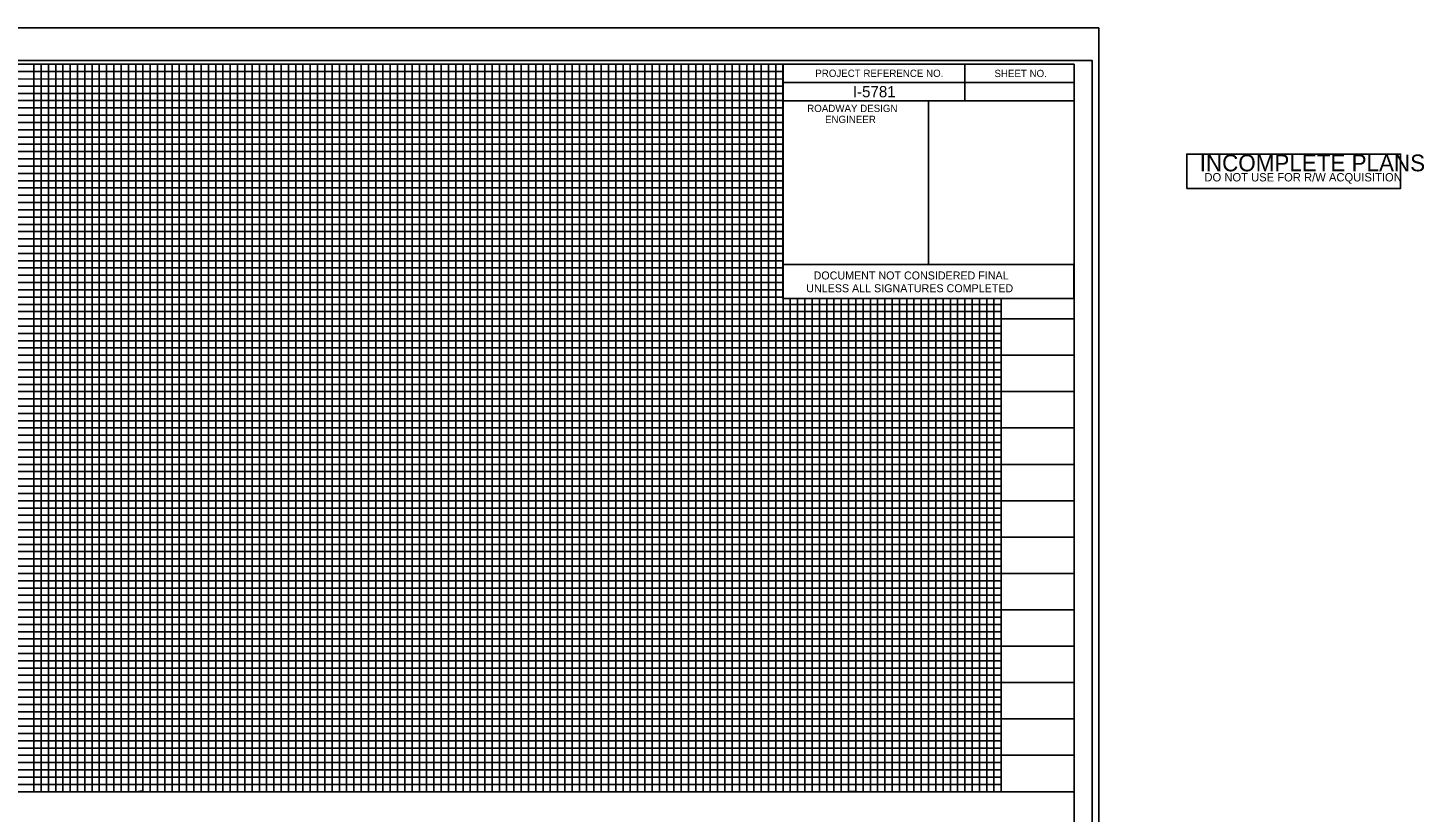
# Model space of a CAD drawing. Extents: x 2327371 to 2329279, y 159556 to 160656.
# Drawn here: x 2328319 to 2329279, y 160117 to 160656 of the extents above; entities that cross this region are included whole.
import ezdxf

# ---------------------------------------------------------------- set-up
doc = ezdxf.new("R2010")
doc.units = 0
for name, color, linetype in [('Scratch_Level_0', 7, 'Continuous'), ('Sheet Cutting Line CELL', 7, 'Continuous'), ('Sheet Data Field CELL', 7, 'Continuous'), ('Sheet DOT Grid CELL', 7, 'Continuous'), ('Sheet Layout Profile Border Port 1', 7, 'Continuous'), ('Sheet Plot Border Inside CELL', 7, 'Continuous'), ('Sheet Plot Border Outside CELL', 7, 'Continuous'), ('Sheet Profile CELL', 7, 'Continuous'), ('Sheet Profile Grid Major CELL', 7, 'Continuous'), ('Sheet Profile Grid Middle CELL', 7, 'Continuous'), ('Sheet Profile Grid Minor CELL', 7, 'Continuous'), ('Sheet Sticker Exception Certification CELL', 7, 'Continuous'), ('Sheet Sticker Incomplete CELL', 7, 'Continuous')]:
    doc.layers.add(name, color=color, linetype=linetype)

msp = doc.modelspace()

# ---------------------------------------------------------------- linework, layer by layer
at = {"layer": 'Scratch_Level_0'}
msp.add_lwpolyline([(2327587.98, 160131.31), (2327587.98, 160631.31), (2328837.98, 160631.31), (2328837.98, 160470.26), (2328987.98, 160470.26), (2328987.98, 160131.31)], close=True, dxfattribs=at)
at = {"layer": 'Sheet Cutting Line CELL'}
msp.add_line((2329054.98, 160656.31), (2327370.98, 160656.31), dxfattribs=at)
at = {"layer": 'Sheet DOT Grid CELL'}
for p, q in [((2328337.98, 160131.31), (2328337.98, 160631.31)), ((2328387.98, 160131.31), (2328387.98, 160631.31)), ((2328437.98, 160131.31), (2328437.98, 160631.31)), ((2328487.98, 160131.31), (2328487.98, 160631.31)), ((2328537.98, 160131.31), (2328537.98, 160631.31)), ((2328587.98, 160131.31), (2328587.98, 160631.31)), ((2328637.98, 160131.31), (2328637.98, 160631.31)), ((2328687.98, 160131.31), (2328687.98, 160631.31)), ((2328737.98, 160131.31), (2328737.98, 160631.31)), ((2328787.98, 160131.31), (2328787.98, 160631.31)), ((2328837.93, 160581.31), (2327537.98, 160581.31)), ((2328837.93, 160531.31), (2327537.98, 160531.31)), ((2328837.98, 160131.31), (2328837.98, 160493.76)), ((2328837.98, 160481.31), (2327537.98, 160481.31)), ((2328887.98, 160131.31), (2328887.98, 160470.26)), ((2328937.98, 160131.31), (2328937.98, 160470.26)), ((2328987.98, 160131.31), (2328987.98, 160470.26)), ((2329037.98, 160431.31), (2327537.98, 160431.31)), ((2329037.98, 160381.31), (2327537.98, 160381.31)), ((2329037.98, 160331.31), (2327537.98, 160331.31)), ((2329037.98, 160281.31), (2327537.98, 160281.31)), ((2329037.98, 160231.31), (2327537.98, 160231.31)), ((2329037.98, 160181.31), (2327537.98, 160181.31))]:
    msp.add_line(p, q, dxfattribs=at)
at = {"layer": 'Sheet Layout Profile Border Port 1'}
msp.add_lwpolyline([(2327587.98, 160470.26), (2327587.98, 160131.31), (2328987.98, 160131.31), (2328987.98, 160470.26)], dxfattribs=at)
at = {"layer": 'Sheet Plot Border Inside CELL'}
msp.add_lwpolyline([(2327383.98, 159578.76), (2329050.48, 159578.76), (2329050.48, 160633.86), (2327383.98, 160633.86)], close=True, dxfattribs=at)
at = {"layer": 'Sheet Plot Border Outside CELL'}
msp.add_lwpolyline([(2327370.98, 159556.31), (2329054.98, 159556.31), (2329054.98, 160656.31), (2327370.98, 160656.31)], close=True, dxfattribs=at)
at = {"layer": 'Sheet Profile CELL'}
for p, q in [((2328962.98, 160631.26), (2328962.98, 160606.26)), ((2328837.93, 160618.76), (2329037.98, 160618.76)), ((2328937.98, 160606.26), (2328937.98, 160493.81)), ((2327537.98, 160131.31), (2329037.98, 160131.31))]:
    msp.add_line(p, q, dxfattribs=at)
for points in [[(2329037.98, 160631.31), (2327537.98, 160631.31), (2327537.98, 159581.31), (2329037.98, 159581.31)], [(2328837.93, 160631.31), (2329037.98, 160631.31), (2329037.98, 160606.26), (2328837.93, 160606.26)], [(2328837.93, 160606.26), (2328937.98, 160606.26), (2328937.98, 160493.76), (2328837.93, 160493.76)], [(2328937.98, 160606.26), (2329037.98, 160606.26), (2329037.98, 160493.76), (2328937.98, 160493.76)]]:
    msp.add_lwpolyline(points, close=True, dxfattribs=at)
at = {"layer": 'Sheet Profile Grid Major CELL'}
for points in [[(2328287.98, 160131.31), (2328337.98, 160131.31), (2328337.98, 160631.31), (2328387.98, 160631.31), (2328387.98, 160131.31), (2328437.98, 160131.31), (2328437.98, 160631.31), (2328487.98, 160631.31), (2328487.98, 160131.31), (2328537.98, 160131.31), (2328537.98, 160631.31), (2328587.98, 160631.31), (2328587.98, 160131.31), (2328637.98, 160131.31), (2328637.98, 160631.31), (2328687.98, 160631.31), (2328687.98, 160131.31), (2328737.98, 160131.31), (2328737.98, 160631.31), (2328787.98, 160631.31), (2328787.98, 160131.31), (2328837.98, 160131.31), (2328837.98, 160631.31), (2328864.28, 160631.31)], [(2327537.98, 160581.31), (2328837.98, 160581.31)], [(2328837.98, 160531.31), (2327537.98, 160531.31), (2327537.98, 160481.31), (2328837.98, 160481.31)], [(2328987.98, 160470.26), (2328987.98, 160131.31), (2329037.98, 160131.31), (2329037.98, 160481.31)], [(2328887.98, 160470.26), (2328887.98, 160131.31), (2328937.98, 160131.31), (2328937.98, 160131.31), (2328937.98, 160470.26)], [(2329037.98, 160431.31), (2327537.98, 160431.31), (2327537.98, 160381.31), (2329037.98, 160381.31)], [(2329037.98, 160331.31), (2327537.98, 160331.31), (2327537.98, 160281.31), (2329037.98, 160281.31)], [(2329037.98, 160231.31), (2327537.98, 160231.31), (2327537.98, 160231.31), (2327537.98, 160181.31), (2329037.98, 160181.31)]]:
    msp.add_lwpolyline(points, dxfattribs=at)
at = {"layer": 'Sheet Profile Grid Middle CELL'}
msp.add_line((2327537.98, 160606.31), (2328837.93, 160606.31), dxfattribs=at)
for points in [[(2328312.98, 160131.31), (2328362.98, 160131.31), (2328362.98, 160631.31), (2328412.98, 160631.31), (2328412.98, 160131.31), (2328462.98, 160131.31), (2328462.98, 160631.31), (2328512.98, 160631.31), (2328512.98, 160131.31), (2328562.98, 160131.31), (2328562.98, 160631.31), (2328612.98, 160631.31), (2328612.98, 160131.31), (2328662.98, 160131.31), (2328662.98, 160631.31), (2328712.98, 160631.31), (2328712.98, 160131.31), (2328762.98, 160131.31), (2328762.98, 160631.31), (2328812.98, 160631.31), (2328812.98, 160131.31), (2328862.98, 160131.31), (2328862.98, 160470.26)], [(2328837.98, 160556.31), (2327537.98, 160556.31), (2327537.98, 160506.31), (2328837.98, 160506.31)], [(2328862.98, 160394.11), (2328862.98, 160131.31), (2328912.98, 160131.31), (2328912.98, 160470.26)], [(2328912.98, 160394.11), (2328912.98, 160131.31), (2328962.98, 160131.31), (2328962.98, 160470.26)], [(2329037.98, 160456.31), (2327537.98, 160456.31), (2327537.98, 160406.31), (2328862.98, 160406.31)], [(2328862.98, 160406.31), (2329037.98, 160406.31)], [(2329037.98, 160356.31), (2327537.98, 160356.31), (2327537.98, 160306.31), (2329037.98, 160306.31)], [(2329037.98, 160256.31), (2327537.98, 160256.31), (2327537.98, 160206.31), (2329037.98, 160206.31)], [(2329037.98, 160156.31), (2327537.98, 160156.31)]]:
    msp.add_lwpolyline(points, dxfattribs=at)
at = {"layer": 'Sheet Profile Grid Minor CELL'}
for p, q in [((2327587.98, 160626.31), (2328837.98, 160626.31)), ((2328837.98, 160621.31), (2327587.98, 160620.96)), ((2327587.98, 160616.31), (2328837.98, 160616.31)), ((2328837.93, 160496.31), (2327587.98, 160496.31)), ((2328837.98, 160491.31), (2327587.98, 160491.31)), ((2328837.98, 160486.31), (2327587.98, 160486.31)), ((2327587.98, 160476.31), (2328837.98, 160476.31)), ((2328837.98, 160471.31), (2327587.98, 160471.31)), ((2327587.98, 160466.31), (2328987.98, 160466.31)), ((2328987.98, 160446.31), (2327587.98, 160446.31)), ((2327587.98, 160441.31), (2328987.98, 160441.31)), ((2328987.98, 160421.31), (2327587.98, 160421.31)), ((2327587.98, 160416.31), (2328987.98, 160416.31)), ((2328987.98, 160396.31), (2327587.98, 160396.31)), ((2327587.98, 160391.31), (2328987.98, 160391.31)), ((2328987.98, 160386.31), (2327587.98, 160386.31)), ((2327587.98, 160376.31), (2328987.98, 160376.31)), ((2328987.98, 160371.31), (2327587.98, 160371.31)), ((2327587.98, 160366.31), (2328987.98, 160366.31)), ((2328987.98, 160361.31), (2327587.98, 160361.31)), ((2327587.98, 160351.31), (2328987.98, 160351.31)), ((2328987.98, 160346.31), (2327587.98, 160346.31)), ((2327587.98, 160341.31), (2328987.98, 160341.31)), ((2328987.98, 160336.31), (2327587.98, 160336.31)), ((2327587.98, 160326.31), (2328987.98, 160326.31)), ((2328987.98, 160321.31), (2327587.98, 160321.31)), ((2327587.98, 160316.31), (2328987.98, 160316.31)), ((2328987.98, 160311.31), (2327587.98, 160311.31)), ((2327587.98, 160301.31), (2328987.98, 160301.31)), ((2328987.98, 160296.31), (2327587.98, 160296.31)), ((2327587.98, 160291.31), (2328987.98, 160291.31)), ((2328987.98, 160286.31), (2327587.98, 160286.31)), ((2327587.98, 160276.31), (2328987.98, 160276.31)), ((2328987.98, 160271.31), (2327587.98, 160271.31)), ((2327587.98, 160266.31), (2328987.98, 160266.31)), ((2328987.98, 160261.31), (2327587.98, 160261.31)), ((2327587.98, 160251.31), (2328987.98, 160251.31)), ((2328987.98, 160246.31), (2327587.98, 160246.31)), ((2328987.98, 160241.31), (2327587.98, 160241.31)), ((2328987.98, 160236.31), (2327587.98, 160236.31)), ((2327587.98, 160226.31), (2328987.98, 160226.31)), ((2328987.98, 160221.31), (2327587.98, 160221.31)), ((2327587.98, 160216.31), (2328987.98, 160216.31)), ((2328987.98, 160211.31), (2327587.98, 160211.31)), ((2327587.98, 160201.31), (2328987.98, 160201.31)), ((2328987.98, 160196.31), (2327587.98, 160196.31)), ((2327587.98, 160191.31), (2328987.98, 160191.31)), ((2328987.98, 160186.31), (2327587.98, 160186.31)), ((2327587.98, 160176.31), (2328987.98, 160176.31)), ((2328987.98, 160171.31), (2327587.98, 160171.31)), ((2327587.98, 160166.31), (2328987.98, 160166.31)), ((2328987.98, 160161.31), (2327587.98, 160161.31)), ((2327587.98, 160151.31), (2328987.98, 160151.31)), ((2328987.98, 160146.31), (2327587.98, 160146.31)), ((2327587.98, 160141.31), (2328987.98, 160141.31))]:
    msp.add_line(p, q, dxfattribs=at)
for points in [[(2328317.98, 160131.31), (2328322.98, 160131.31), (2328322.98, 160631.31), (2328327.98, 160631.31), (2328327.98, 160131.31), (2328332.98, 160131.31), (2328332.98, 160631.31), (2328342.98, 160631.31), (2328342.98, 160131.31), (2328347.98, 160131.31), (2328347.98, 160631.31), (2328352.98, 160631.31), (2328352.98, 160131.31), (2328357.98, 160131.31), (2328357.98, 160631.31), (2328367.98, 160631.31), (2328367.98, 160131.31), (2328372.98, 160131.31), (2328372.98, 160631.31), (2328377.98, 160631.31), (2328377.98, 160131.31), (2328382.98, 160131.31), (2328382.98, 160631.31), (2328392.98, 160631.31), (2328392.98, 160131.31), (2328397.68, 160131.86), (2328397.98, 160131.31), (2328397.98, 160631.31), (2328402.98, 160631.31), (2328402.98, 160131.31), (2328407.98, 160131.31), (2328407.98, 160631.31), (2328417.98, 160631.31), (2328417.98, 160131.31), (2328422.98, 160131.31)], [(2328422.98, 160131.31), (2328422.98, 160631.31), (2328427.98, 160631.31), (2328427.98, 160131.31), (2328432.98, 160131.31), (2328432.98, 160631.31), (2328442.98, 160631.31), (2328442.98, 160131.31), (2328447.98, 160131.31), (2328447.98, 160631.31), (2328452.98, 160631.31), (2328452.98, 160131.31), (2328457.98, 160131.31), (2328457.98, 160631.31), (2328467.98, 160631.31), (2328467.98, 160131.31), (2328472.98, 160131.31), (2328472.98, 160631.31), (2328477.98, 160631.31), (2328477.98, 160131.31), (2328482.98, 160131.31), (2328482.98, 160631.31), (2328492.98, 160631.31), (2328492.98, 160131.31), (2328497.98, 160131.31), (2328497.98, 160631.31), (2328502.98, 160631.31), (2328502.98, 160131.31), (2328507.98, 160131.31), (2328507.98, 160631.31), (2328517.98, 160631.31), (2328517.98, 160131.31), (2328522.98, 160131.31), (2328522.98, 160631.31), (2328527.98, 160631.31), (2328527.98, 160131.31), (2328532.98, 160131.31), (2328532.98, 160631.31), (2328542.98, 160631.31), (2328542.98, 160131.31), (2328547.98, 160131.31), (2328547.98, 160631.31), (2328552.98, 160631.31), (2328552.98, 160131.31), (2328557.98, 160131.31), (2328557.98, 160631.31), (2328567.98, 160631.31), (2328567.98, 160131.31), (2328572.98, 160131.31), (2328572.98, 160631.31), (2328577.98, 160631.31), (2328577.98, 160131.31), (2328582.98, 160131.31), (2328582.98, 160631.31), (2328592.98, 160631.31), (2328592.98, 160131.31), (2328597.98, 160131.31), (2328597.98, 160631.31), (2328602.98, 160631.31), (2328602.98, 160131.31), (2328607.98, 160131.31), (2328607.98, 160631.31), (2328617.98, 160631.31), (2328617.98, 160131.31), (2328622.98, 160131.31), (2328622.98, 160631.31), (2328627.98, 160631.31), (2328627.98, 160131.31), (2328632.98, 160131.31), (2328632.98, 160631.31), (2328642.98, 160631.31), (2328642.98, 160131.31), (2328647.98, 160131.31), (2328647.98, 160631.31), (2328652.98, 160631.31), (2328652.98, 160131.31), (2328657.98, 160131.31), (2328657.98, 160631.31), (2328667.98, 160631.31), (2328667.98, 160131.31), (2328672.98, 160131.31), (2328672.98, 160631.31), (2328677.98, 160631.31), (2328677.98, 160131.31), (2328682.98, 160131.31), (2328682.98, 160631.31), (2328692.98, 160631.31), (2328692.98, 160131.31), (2328697.98, 160131.31), (2328697.98, 160631.31), (2328702.98, 160631.31), (2328702.98, 160131.31), (2328707.98, 160131.31), (2328707.98, 160631.31), (2328717.98, 160631.31), (2328717.98, 160131.31), (2328722.98, 160131.31), (2328722.98, 160631.31), (2328727.98, 160631.31), (2328727.98, 160131.31)], [(2328727.98, 160131.31), (2328732.98, 160131.31), (2328732.98, 160631.31), (2328742.98, 160631.31), (2328742.98, 160131.31), (2328747.98, 160131.31), (2328747.98, 160631.31), (2328752.98, 160631.31), (2328752.98, 160131.31), (2328757.98, 160131.31), (2328757.98, 160631.31), (2328767.98, 160631.31), (2328767.98, 160131.31), (2328772.98, 160131.31), (2328772.98, 160631.31), (2328777.98, 160631.31), (2328777.98, 160131.31), (2328782.98, 160131.31), (2328782.98, 160631.31), (2328792.98, 160631.31), (2328792.98, 160131.31), (2328797.98, 160131.31), (2328797.98, 160631.31), (2328802.98, 160631.31), (2328802.98, 160131.31), (2328807.98, 160131.31), (2328807.98, 160631.31), (2328817.98, 160631.31), (2328817.98, 160131.31), (2328822.98, 160131.31), (2328822.98, 160631.31), (2328827.98, 160631.31), (2328827.98, 160131.31), (2328832.98, 160131.31), (2328832.98, 160631.31), (2328842.98, 160631.31)], [(2328837.98, 160611.31), (2327587.98, 160611.31), (2327587.98, 160601.31), (2328837.98, 160601.31)], [(2328837.93, 160596.31), (2327587.98, 160596.31), (2327587.98, 160591.31), (2328837.98, 160591.31)], [(2328837.98, 160586.31), (2327587.98, 160586.31), (2327587.98, 160576.31), (2328837.98, 160576.31)], [(2328837.98, 160571.31), (2327587.98, 160571.31), (2327587.98, 160566.31), (2328837.98, 160566.31)], [(2328837.98, 160561.31), (2327587.98, 160561.31), (2327587.98, 160551.31), (2328837.98, 160551.31)], [(2328837.98, 160546.31), (2327587.98, 160546.31), (2327587.98, 160541.31), (2328837.98, 160541.31)], [(2328837.98, 160536.31), (2327587.98, 160536.31), (2327587.98, 160526.31), (2328837.98, 160526.31)], [(2328837.98, 160521.21), (2327588.08, 160521.21), (2327588.08, 160516.31), (2328837.98, 160516.31)], [(2328837.98, 160511.31), (2327587.98, 160511.31), (2327587.98, 160501.31), (2328837.98, 160501.31)], [(2328842.98, 160470.26), (2328842.98, 160131.31), (2328847.98, 160131.31), (2328847.98, 160470.26)], [(2328852.98, 160470.26), (2328852.98, 160131.31), (2328857.98, 160131.31), (2328857.98, 160470.26)], [(2328867.98, 160470.26), (2328867.98, 160131.31), (2328867.98, 160131.31), (2328872.98, 160131.31), (2328877.98, 160131.31), (2328877.98, 160470.26)], [(2328872.98, 160470.26), (2328872.98, 160131.31)], [(2328882.98, 160470.26), (2328882.88, 160131.36), (2328887.88, 160131.36), (2328892.98, 160131.31), (2328892.98, 160470.26)], [(2328892.98, 160394.11), (2328892.98, 160131.31), (2328897.98, 160131.31), (2328897.98, 160470.26)], [(2328902.98, 160470.26), (2328902.98, 160131.31), (2328907.98, 160131.31), (2328907.98, 160470.26)], [(2328917.98, 160470.26), (2328917.98, 160131.31), (2328922.98, 160131.31), (2328922.98, 160470.26)], [(2328927.98, 160470.26), (2328927.98, 160131.31), (2328932.98, 160131.31), (2328932.98, 160470.26)], [(2328942.98, 160470.26), (2328942.98, 160131.31), (2328947.98, 160131.31), (2328947.98, 160470.26)], [(2328952.98, 160470.26), (2328952.98, 160131.31), (2328957.98, 160131.31), (2328957.98, 160470.26)], [(2328967.98, 160470.26), (2328967.98, 160131.31), (2328972.98, 160131.31), (2328972.98, 160470.26)], [(2328977.98, 160470.26), (2328977.98, 160131.31), (2328982.98, 160131.31), (2328982.98, 160470.26)], [(2328987.98, 160461.31), (2327587.98, 160461.31), (2327587.98, 160451.31), (2328987.98, 160451.31)], [(2328987.98, 160436.31), (2327587.98, 160436.31), (2327587.98, 160426.31), (2328987.98, 160426.31)], [(2328987.98, 160411.31), (2327587.98, 160411.31), (2327587.98, 160401.31), (2328987.98, 160401.31)], [(2328987.98, 160136.31), (2327587.98, 160136.31)]]:
    msp.add_lwpolyline(points, dxfattribs=at)
at = {"layer": 'Sheet Sticker Exception Certification CELL'}
for p, q in [((2328837.93, 160470.26), (2328837.93, 160493.76)), ((2328837.93, 160493.76), (2329037.97, 160493.76)), ((2328837.93, 160470.26), (2328837.93, 160493.76)), ((2328837.93, 160493.76), (2329037.97, 160493.76)), ((2329037.97, 160493.74), (2329037.97, 160470.24)), ((2329037.97, 160493.74), (2329037.97, 160470.24)), ((2329037.97, 160470.26), (2328837.93, 160470.26)), ((2329037.97, 160470.26), (2328837.93, 160470.26))]:
    msp.add_line(p, q, dxfattribs=at)
at = {"layer": 'Sheet Sticker Incomplete CELL'}
msp.add_lwpolyline([(2329115.43, 160546.04), (2329115.43, 160569.54), (2329262.43, 160569.54), (2329262.43, 160546.04)], close=True, dxfattribs=at)

# ---------------------------------------------------------------- texts
at = {"layer": 'Sheet Data Field CELL'}
msp.add_text('I-5781', height=7.75, dxfattribs=at).set_placement((2328885.98, 160608.62))
at = {"layer": 'Sheet Profile CELL'}
for s, height, p in [('PROJECT REFERENCE NO.', 5.0001, (2328860.14, 160622.62)), ('SHEET NO.', 5, (2328983.29, 160622.52)), ('ROADWAY DESIGN', 5.0001, (2328854.59, 160598.52)), ('ENGINEER', 5, (2328866.84, 160590.92))]:
    msp.add_text(s, height=height, dxfattribs=at).set_placement(p)
at = {"layer": 'Sheet Sticker Exception Certification CELL'}
for s, p in [('DOCUMENT NOT CONSIDERED FINAL', (2328859, 160483.41)), ('DOCUMENT NOT CONSIDERED FINAL', (2328859, 160483.41)), ('UNLESS ALL SIGNATURES COMPLETED', (2328853.93, 160474.61)), ('UNLESS ALL SIGNATURES COMPLETED', (2328853.93, 160474.61))]:
    msp.add_text(s, height=5.5, dxfattribs=at).set_placement(p)
at = {"layer": 'Sheet Sticker Incomplete CELL'}
for s, height, p in [('INCOMPLETE PLANS', 11.52, (2329124.38, 160557.74)), ('DO NOT USE FOR R/W ACQUISITION', 5.76, (2329127.63, 160550.79))]:
    msp.add_text(s, height=height, dxfattribs=at).set_placement(p)

doc.saveas('drawing.dxf')
